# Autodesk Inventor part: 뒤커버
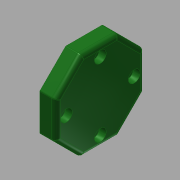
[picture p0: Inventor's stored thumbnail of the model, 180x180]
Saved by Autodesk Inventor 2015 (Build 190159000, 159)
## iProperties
Created: 2015-11
Part Number: 뒤커버
Material: 알루미늄 6061
Document SubType Name: Modeling
Designer: mduedu
Density: 1 g/cm^3
Appearance: 매끄러움 - 짙은 산림 녹색
Author: mduedu
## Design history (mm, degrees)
sketch "스케치5" dims "d66" = 60
  geometry: L1 (12.426, 30)-(30, 12.426); L2 (30, 12.426)-(30, -12.426); L3 (30, -12.426)-(12.426, -30); L4 (12.426, -30)-(-12.426, -30); L5 (-12.426, -30)-(-30, -12.426); L6 (-30, -12.426)-(-30, 12.426); L7 (-30, 12.426)-(-12.426, 30); L8 (-12.426, 30)-(12.426, 30); 4 further points
  constraints: 16 end point, 2 coincident, 2 vertical alignment, 1 midpoint, 19 other
extrude "돌출2" new body sketch "스케치5" distance "d67" = 11; taper "d68" = 0 deg
sketch "스케치6"
  geometry: C1 r 16 at (0, 0); 1 further point
  constraints: 1 centre point, 1 coincident
  dimensions: "d69" = 32 diameter of C1
extrude "돌출3" join sketch "스케치6" distance "d70" = 3; taper "d71" = 0 deg
hole "구멍5" diameter "d74" = 25; stored, may be unused: countersink angle "d78" = 90 deg, drill point angle "d80" = 0 deg; dims "d72" = 10, "d73" = 10, "d75" = 6, "d76" = 4, "d77" = 2, "d79" = 10
fillet "모깎기7" dims "d81" = 1
fillet "모깎기8" dims "d82" = 3
fillet "모깎기9" dims "d83" = 3
fillet "모깎기10" dims "d84" = 0.3
sketch "스케치7" dims "d85" = 46
  geometry: 3 further points
  constraints: 2 vertical alignment, 1 coincident, 2 other
hole "구멍6" sketch "스케치7" at (0, 23) diameter "d86" = 4.5; stored, may be unused: countersink angle "d90" = 90 deg, drill point angle "d92" = 0 deg; dims "d87" = 6, "d88" = 8, "d89" = 4.6, "d91" = 10
node "솔리드2"
pattern_circular "원형 패턴3" dims angle "d94" = 360 deg
